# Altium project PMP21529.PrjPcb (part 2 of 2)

## Sheet PMP21529_Hardware.SchDoc
size 431 x 279 mm; Date: Not shown in title block; ApprovedBy: Not shown in title block; CheckedBy: Not shown in title block; Author: Not shown in title block; CompanyName: Not shown in title block; DrawnBy: Bosheng Sun; Engineer: Not shown in title block; Organization: Not shown in title block; Address1: Not shown in title block; Address2: Not shown in title block; Address3: Not shown in title block; Address4: Not shown in title block; DocumentNumber: 1; Revision: Use project parameter SCH_Rev; SheetNumber: 3; SheetTotal: 3; PageSetup: Record=PageOptions¦CenterHorizontal=True¦CenterVertical=True¦PrintScale=1.00¦XCorrection=1.00¦YCorrection=1.00¦PrintKind=0¦BorderSize=5000000¦LeftOffset=0¦BottomOffset=0¦Orientation=2¦PaperLength=1000¦PaperWidth=1000¦Scale=100¦PaperSource=15¦PrintQuality=600¦MediaType=1¦DitherType=10¦PaperKind=Letter¦PrintScaleMode=1
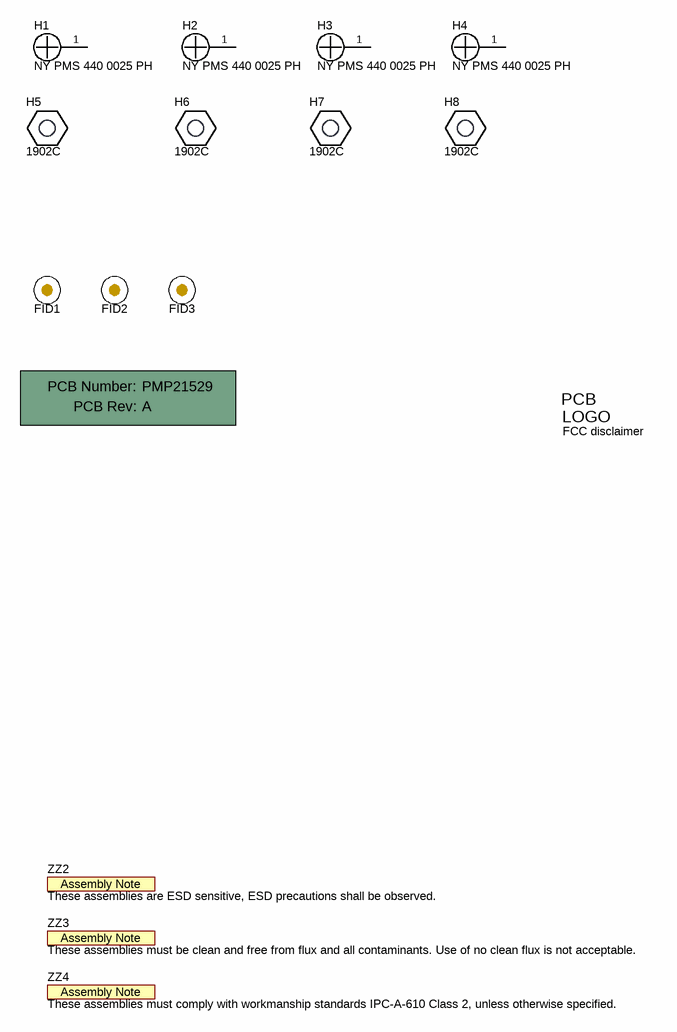
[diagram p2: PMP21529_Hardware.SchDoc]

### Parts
!PCB1  Printed Circuit Board  (value not drawn)  (mechanical)
FID1  Fiducial  [Fiducial10-20]  (value not drawn)
FID2  Fiducial  [Fiducial10-20]  (value not drawn)
FID3  Fiducial  [Fiducial10-20]  (value not drawn)
H1  NY PMS 440 0025 PH  [NY PMS 440 0025 PH]
H2  NY PMS 440 0025 PH  [NY PMS 440 0025 PH]
H3  NY PMS 440 0025 PH  [NY PMS 440 0025 PH]
H4  NY PMS 440 0025 PH  [NY PMS 440 0025 PH]
H5  1902C  [Keystone_1902C]
H6  1902C  [Keystone_1902C]
H7  1902C  [Keystone_1902C]
H8  1902C  [Keystone_1902C]
Logo3  FCC disclaimer  [FCC_disclaimer]  (no BOM)
ZZ2  These assemblies are ESD sensitive, ESD precautions shall be observed.  [AssemblyNote]  (no BOM)
ZZ3  These assemblies must be clean and free from flux and all contaminants. Use of no clean flux is not acceptable.  [AssemblyNote]  (no BOM)
ZZ4  These assemblies must comply with workmanship standards IPC-A-610 Class 2, unless otherwise specified.  [AssemblyNote]  (no BOM)

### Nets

Not connected (* = marked no-connect by the designer): H1 1; H2 1; H3 1; H4 1

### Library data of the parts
!PCB1 = CMP-0003618-2: Manufacturer: Any; PartNumber: PMP21529
FID1-FID3 = CMP-0077181-1: Fiducial mark.  There is nothing to buy or mount.
H1-H4 = CMP-0003617-1: Machine Screw, Round, #4-40 x 1/4, Nylon, Philips panhead; Manufacturer: B&F Fastener Supply; CompType: Hardware
H5-H8 = CMP-0003610-1: Standoff, Hex, 0.5"L #4-40 Nylon; Manufacturer: Keystone; CompType: Hardware
Logo3 = CMP-0074847-1: FCC_disclaimer; Library Reference: Logo
ZZ2 = CMP-0077236-1
ZZ3 = CMP-0077237-1
ZZ4 = CMP-0077238-1

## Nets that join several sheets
12V: PMP21529_Sheet1 (10 pins), PMP21529_Sheet2 (8 pins)
AGND: PMP21529_Sheet1 (18 pins), PMP21529_Sheet2 (45 pins)
PGND: PMP21529_Sheet1 (39 pins), PMP21529_Sheet2 (17 pins)
CBC1: PMP21529_Sheet1 (C17.1 R15.2), PMP21529_Sheet2 (U7.4)
CBC2: PMP21529_Sheet1 (C18.1 R20.2), PMP21529_Sheet2 (U7.3)
DPWM0A: PMP21529_Sheet1 (U1.5), PMP21529_Sheet2 (U7.11)
DPWM0B: PMP21529_Sheet1 (U1.6), PMP21529_Sheet2 (U7.12)
DPWM1A: PMP21529_Sheet1 (U4.5), PMP21529_Sheet2 (U7.13)
DPWM1B: PMP21529_Sheet1 (U4.6), PMP21529_Sheet2 (U7.14)
Iout1: PMP21529_Sheet1 (C20.1 R23.2), PMP21529_Sheet2 (U7.38)
Iout2: PMP21529_Sheet1 (C22.1 R24.2), PMP21529_Sheet2 (U7.2)
Iout2_sense: PMP21529_Sheet1 (C26.1 R28.1 R32.2), PMP21529_Sheet2 (U7.33)
V1+: PMP21529_Sheet1 (9 pins), PMP21529_Sheet2 (D5.2 R1.2)
V2+: PMP21529_Sheet1 (9 pins), PMP21529_Sheet2 (D7.2 R2.2)

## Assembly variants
001: not fitted C62 C63 D7 D13 D14 FID1 FID2 FID3 R60 R61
